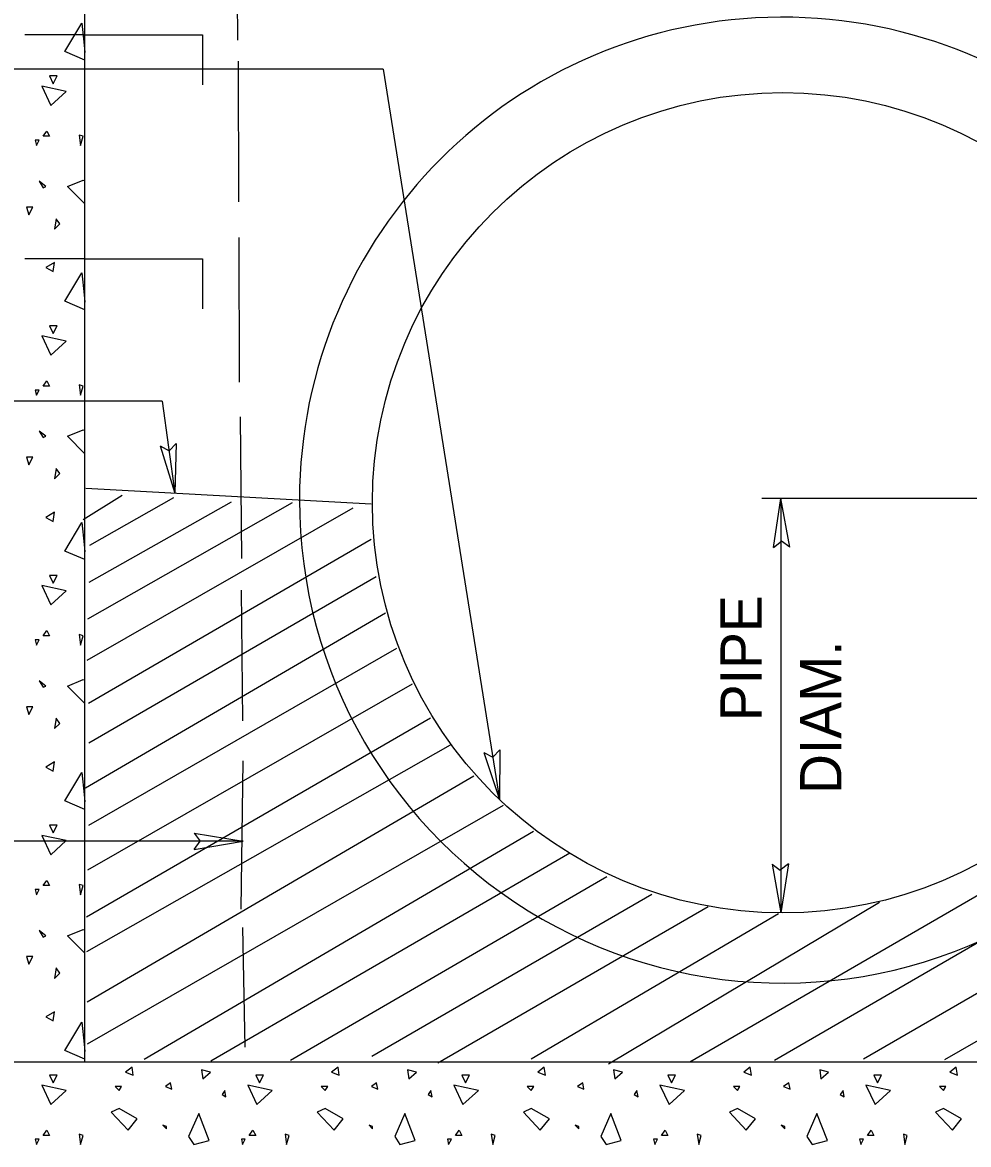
# Model space of a CAD drawing. Extents: x 8.6 to 15.9, y 6.4 to 16.6.
# Drawn here: x 9.57 to 10.943, y 9.729 to 11.359 of the extents above; entities that cross this region are included whole.
import ezdxf

# ---------------------------------------------------------------- set-up
doc = ezdxf.new("R2010")
doc.units = 0
for name, color, linetype in [('DETL-DIMS', 7, 'Continuous'), ('DETL-LINE', 7, 'Continuous'), ('DETL-NOTE', 7, 'Continuous'), ('DETL-PATT', 7, 'Continuous')]:
    doc.layers.add(name, color=color, linetype=linetype)

msp = doc.modelspace()

# ---------------------------------------------------------------- linework, layer by layer
at = {"layer": 'DETL-DIMS'}
for p, q in [((10.0933, 11.2907), (9.2646, 11.2907)), ((10.0933, 11.2907), (10.2623, 10.2305)), ((9.7729, 10.8086), (8.8878, 10.8086)), ((9.7729, 10.8086), (9.7911, 10.6752)), ((9.7698, 10.7441), (9.7911, 10.6752)), ((9.7698, 10.7441), (9.7827, 10.7369)), ((9.7932, 10.7473), (9.7827, 10.7369)), ((9.7932, 10.7473), (9.7911, 10.6752)), ((11.2135, 10.6676), (10.643, 10.6676)), ((10.6599, 10.5964), (10.6708, 10.6676)), ((10.6836, 10.5967), (10.6708, 10.6676)), ((10.6708, 10.6676), (10.6708, 10.0658)), ((10.6599, 10.5964), (10.6716, 10.6054)), ((10.6836, 10.5967), (10.6716, 10.6054)), ((10.2394, 10.2988), (10.2623, 10.2305)), ((10.2394, 10.2988), (10.2525, 10.2919)), ((10.2628, 10.3025), (10.2525, 10.2919)), ((10.2628, 10.3025), (10.2623, 10.2305)), ((9.8902, 10.1701), (9.273, 10.1701)), ((9.819, 10.1815), (9.8902, 10.1701)), ((9.819, 10.1815), (9.828, 10.1697)), ((9.8192, 10.1578), (9.8902, 10.1701)), ((9.8192, 10.1578), (9.828, 10.1697)), ((10.6579, 10.1367), (10.6708, 10.0658)), ((10.6579, 10.1367), (10.6699, 10.128)), ((10.6816, 10.137), (10.6699, 10.128)), ((10.6816, 10.137), (10.6708, 10.0658))]:
    msp.add_line(p, q, dxfattribs=at)
at = {"layer": 'DETL-LINE'}
for p, q in [((9.6604, 9.8494), (9.6604, 13.5991)), ((9.8827, 11.3331), (9.8814, 11.438)), ((9.6604, 11.3407), (9.5735, 11.3407)), ((9.8838, 11.0984), (9.8833, 11.3025)), ((9.8851, 10.8364), (9.8843, 11.0467)), ((9.6604, 11.0153), (9.5735, 11.0153)), ((9.8884, 10.5805), (9.8865, 10.7861)), ((9.6618, 10.6823), (10.0762, 10.6597)), ((9.8899, 10.3448), (9.8876, 10.5342)), ((9.8871, 10.0714), (9.8902, 10.2864)), ((9.8933, 9.871), (9.89, 10.0445)), ((9.5295, 9.8494), (11.8146, 9.8494))]:
    msp.add_line(p, q, dxfattribs=at)
for points in [[(9.6604, 11.3407), (9.8311, 11.3407), (9.8311, 11.2681)], [(9.6604, 11.0153), (9.8311, 11.0153), (9.8311, 10.9427)]]:
    msp.add_lwpolyline(points, dxfattribs=at)
msp.add_circle((10.6735, 10.6613), 0.5956, dxfattribs=at)
for start, end in [(0.6006, 179.9414), (179.9414, 0.6006)]:
    msp.add_arc((10.6733, 10.6651), 0.7013, start, end, dxfattribs=at)
at = {"layer": 'DETL-PATT'}
for p, q in [((9.6582, 10.6372), (9.7144, 10.6721)), ((9.9613, 10.6611), (9.6644, 10.4922)), ((9.6666, 10.5458), (9.8735, 10.6628)), ((9.7889, 10.6684), (9.6672, 10.5994)), ((9.6638, 10.4328), (10.0499, 10.6541)), ((10.0761, 10.6078), (9.6659, 10.3698)), ((9.6662, 10.3127), (10.0831, 10.5541)), ((10.0968, 10.5008), (9.6616, 10.2471)), ((10.5385, 9.8495), (11.6688, 10.504)), ((9.6664, 10.1934), (10.1132, 10.4502)), ((11.6695, 10.4348), (10.6613, 9.8515)), ((10.1357, 10.3981), (9.6644, 10.1279)), ((10.7908, 9.8539), (11.6706, 10.3639)), ((9.6629, 10.0601), (10.1623, 10.3491)), ((10.1908, 10.3094), (9.6629, 10.0091)), ((11.6677, 10.29), (10.9083, 9.8525)), ((9.6639, 9.9364), (10.2249, 10.2648)), ((10.2675, 10.2215), (9.6638, 9.8752)), ((9.7465, 9.8532), (10.3115, 10.1843)), ((9.8432, 9.8511), (10.3644, 10.1532)), ((10.4182, 10.1182), (9.9589, 9.8514)), ((10.0769, 9.8579), (10.4836, 10.0928)), ((10.5654, 10.0744), (10.173, 9.8478)), ((10.8138, 10.0807), (10.4205, 9.8461)), ((10.3083, 9.8541), (10.6673, 10.0651))]:
    msp.add_line(p, q, dxfattribs=at)
for points in [[(9.6604, 11.304), (9.6316, 11.3165), (9.656, 11.3578), (9.6596, 11.3258), (9.6604, 11.3152)], [(9.6604, 11.0952), (9.6351, 11.1205), (9.6578, 11.1298), (9.6604, 11.1292)], [(9.6604, 10.9414), (9.6316, 10.9538), (9.656, 10.9952), (9.6596, 10.9632), (9.6604, 10.9525)], [(9.6604, 10.7325), (9.6351, 10.7578), (9.6578, 10.7672), (9.6604, 10.7665)], [(9.6604, 10.5787), (9.6316, 10.5912), (9.656, 10.6325), (9.6596, 10.6005), (9.6604, 10.5899)], [(9.6604, 10.3699), (9.6351, 10.3952), (9.6578, 10.4045), (9.6604, 10.4038)], [(9.6604, 10.216), (9.6316, 10.2285), (9.656, 10.2698), (9.6596, 10.2378), (9.6604, 10.2272)], [(9.6604, 10.0072), (9.6351, 10.0325), (9.6578, 10.0418), (9.6604, 10.0412)], [(9.6604, 9.8534), (9.6316, 9.8658), (9.656, 9.9072), (9.6596, 9.8752), (9.6604, 9.8645)]]:
    msp.add_lwpolyline(points, dxfattribs=at)
for points in [[(9.6093, 11.281), (9.6147, 11.2698), (9.6205, 11.281)], [(9.5978, 11.2663), (9.6111, 11.2383), (9.6333, 11.2587)], [(9.6053, 11.201), (9.6093, 11.1934), (9.6, 11.1934)], [(9.652, 11.1952), (9.6542, 11.1801), (9.6578, 11.1934)], [(9.5885, 11.1876), (9.5902, 11.1801), (9.5942, 11.1876)], [(9.6, 11.1187), (9.6036, 11.1205), (9.5942, 11.1281)], [(9.5756, 11.0903), (9.5791, 11.0792), (9.5849, 11.0903)], [(9.6187, 11.0738), (9.6165, 11.0587), (9.624, 11.0663)], [(9.6036, 11.0027), (9.6147, 10.997), (9.6165, 11.0103)], [(9.6093, 10.9183), (9.6147, 10.9072), (9.6205, 10.9183)], [(9.5978, 10.9036), (9.6111, 10.8756), (9.6333, 10.8961)], [(9.6053, 10.8383), (9.6093, 10.8307), (9.6, 10.8307)], [(9.5885, 10.825), (9.5902, 10.8174), (9.5942, 10.825)], [(9.652, 10.8325), (9.6542, 10.8174), (9.6578, 10.8307)], [(9.6, 10.7561), (9.6036, 10.7578), (9.5942, 10.7654)], [(9.5756, 10.7276), (9.5791, 10.7165), (9.5849, 10.7276)], [(9.6187, 10.7112), (9.6165, 10.6961), (9.624, 10.7036)], [(9.6036, 10.6401), (9.6147, 10.6343), (9.6165, 10.6476)], [(9.6093, 10.5556), (9.6147, 10.5445), (9.6205, 10.5556)], [(9.5978, 10.541), (9.6111, 10.513), (9.6333, 10.5334)], [(9.5885, 10.4623), (9.5902, 10.4547), (9.5942, 10.4623)], [(9.6053, 10.4756), (9.6093, 10.4681), (9.6, 10.4681)], [(9.652, 10.4698), (9.6542, 10.4547), (9.6578, 10.4681)], [(9.6, 10.3934), (9.6036, 10.3952), (9.5942, 10.4027)], [(9.5756, 10.365), (9.5791, 10.3538), (9.5849, 10.365)], [(9.6187, 10.3485), (9.6165, 10.3334), (9.624, 10.341)], [(9.6036, 10.2774), (9.6147, 10.2716), (9.6165, 10.285)], [(9.6093, 10.193), (9.6147, 10.1818), (9.6205, 10.193)], [(9.5978, 10.1783), (9.6111, 10.1503), (9.6333, 10.1707)], [(9.6053, 10.113), (9.6093, 10.1054), (9.6, 10.1054)], [(9.652, 10.1072), (9.6542, 10.0921), (9.6578, 10.1054)], [(9.5885, 10.0996), (9.5902, 10.0921), (9.5942, 10.0996)], [(9.6, 10.0307), (9.6036, 10.0325), (9.5942, 10.0401)], [(9.5756, 10.0023), (9.5791, 9.9912), (9.5849, 10.0023)], [(9.6187, 9.9858), (9.6165, 9.9707), (9.624, 9.9783)], [(9.6036, 9.9147), (9.6147, 9.909), (9.6165, 9.9223)], [(9.7289, 9.8418), (9.7196, 9.8343), (9.7307, 9.8303)], [(10.028, 9.8418), (10.0187, 9.8343), (10.0298, 9.8303)], [(10.3271, 9.8418), (10.3178, 9.8343), (10.3289, 9.8303)], [(10.6262, 9.8418), (10.6169, 9.8343), (10.628, 9.8303)], [(10.9253, 9.8418), (10.916, 9.8343), (10.9271, 9.8303)], [(9.6093, 9.8303), (9.6147, 9.8192), (9.6205, 9.8303)], [(9.8298, 9.8378), (9.8316, 9.825), (9.8427, 9.8343)], [(9.9085, 9.8303), (9.9138, 9.8192), (9.9196, 9.8303)], [(10.1289, 9.8378), (10.1307, 9.825), (10.1418, 9.8343)], [(10.2076, 9.8303), (10.2129, 9.8192), (10.2187, 9.8303)], [(10.428, 9.8378), (10.4298, 9.825), (10.4409, 9.8343)], [(10.5067, 9.8303), (10.512, 9.8192), (10.5178, 9.8303)], [(10.7271, 9.8378), (10.7289, 9.825), (10.74, 9.8343)], [(10.8058, 9.8303), (10.8111, 9.8192), (10.8169, 9.8303)], [(9.5978, 9.8156), (9.6111, 9.7876), (9.6333, 9.8081)], [(9.7045, 9.8138), (9.7102, 9.8081), (9.7138, 9.8138)], [(9.7773, 9.8138), (9.7867, 9.8098), (9.7849, 9.8192)], [(9.8969, 9.8156), (9.9102, 9.7876), (9.9325, 9.8081)], [(10.0036, 9.8138), (10.0093, 9.8081), (10.0129, 9.8138)], [(10.0765, 9.8138), (10.0858, 9.8098), (10.084, 9.8192)], [(10.196, 9.8156), (10.2093, 9.7876), (10.2316, 9.8081)], [(10.3027, 9.8138), (10.3085, 9.8081), (10.312, 9.8138)], [(10.3756, 9.8138), (10.3849, 9.8098), (10.3831, 9.8192)], [(10.4951, 9.8156), (10.5085, 9.7876), (10.5307, 9.8081)], [(10.6018, 9.8138), (10.6076, 9.8081), (10.6111, 9.8138)], [(10.6747, 9.8138), (10.684, 9.8098), (10.6822, 9.8192)], [(10.7942, 9.8156), (10.8076, 9.7876), (10.8298, 9.8081)], [(10.9009, 9.8138), (10.9067, 9.8081), (10.9102, 9.8138)], [(9.8596, 9.8023), (9.8653, 9.7987), (9.8636, 9.8081)], [(10.1587, 9.8023), (10.1645, 9.7987), (10.1627, 9.8081)], [(10.4578, 9.8023), (10.4636, 9.7987), (10.4618, 9.8081)], [(10.7569, 9.8023), (10.7627, 9.7987), (10.7609, 9.8081)], [(9.6987, 9.7765), (9.7231, 9.7503), (9.7365, 9.7667), (9.7102, 9.7818)], [(9.9978, 9.7765), (10.0222, 9.7503), (10.0356, 9.7667), (10.0093, 9.7818)], [(10.2969, 9.7765), (10.3213, 9.7503), (10.3347, 9.7667), (10.3085, 9.7818)], [(10.596, 9.7765), (10.6205, 9.7503), (10.6338, 9.7667), (10.6076, 9.7818)], [(10.8951, 9.7765), (10.9196, 9.7503), (10.9329, 9.7667), (10.9067, 9.7818)], [(9.8187, 9.7294), (9.8409, 9.7352), (9.8258, 9.7743), (9.8111, 9.741)], [(10.1178, 9.7294), (10.14, 9.7352), (10.1249, 9.7743), (10.1102, 9.741)], [(10.4169, 9.7294), (10.4391, 9.7352), (10.424, 9.7743), (10.4093, 9.741)], [(10.716, 9.7294), (10.7382, 9.7352), (10.7231, 9.7743), (10.7085, 9.741)], [(9.6053, 9.7503), (9.6093, 9.7427), (9.6, 9.7427)], [(9.652, 9.7445), (9.6542, 9.7294), (9.6578, 9.7427)], [(9.7791, 9.7556), (9.7738, 9.7574), (9.7791, 9.7521)], [(9.9045, 9.7503), (9.9085, 9.7427), (9.8991, 9.7427)], [(9.9511, 9.7445), (9.9533, 9.7294), (9.9569, 9.7427)], [(10.0782, 9.7556), (10.0729, 9.7574), (10.0782, 9.7521)], [(10.2036, 9.7503), (10.2076, 9.7427), (10.1982, 9.7427)], [(10.2502, 9.7445), (10.2525, 9.7294), (10.256, 9.7427)], [(10.3773, 9.7556), (10.372, 9.7574), (10.3773, 9.7521)], [(10.5027, 9.7503), (10.5067, 9.7427), (10.4973, 9.7427)], [(10.5493, 9.7445), (10.5516, 9.7294), (10.5551, 9.7427)], [(10.6765, 9.7556), (10.6711, 9.7574), (10.6765, 9.7521)], [(10.8018, 9.7503), (10.8058, 9.7427), (10.7965, 9.7427)], [(10.8485, 9.7445), (10.8507, 9.7294), (10.8542, 9.7427)], [(9.5885, 9.737), (9.5902, 9.7294), (9.5942, 9.737)], [(9.8876, 9.737), (9.8893, 9.7294), (9.8933, 9.737)], [(10.1867, 9.737), (10.1885, 9.7294), (10.1925, 9.737)], [(10.4858, 9.737), (10.4876, 9.7294), (10.4916, 9.737)], [(10.7849, 9.737), (10.7867, 9.7294), (10.7907, 9.737)]]:
    msp.add_lwpolyline(points, close=True, dxfattribs=at)

# ---------------------------------------------------------------- texts
at = {"layer": 'DETL-NOTE'}
for s, p in [('PIPE', (10.643, 10.3442)), ('DIAM.', (10.7586, 10.2384))]:
    msp.add_text(s, height=0.06, rotation=90, dxfattribs=at).set_placement(p)

doc.saveas('drawing.dxf')
